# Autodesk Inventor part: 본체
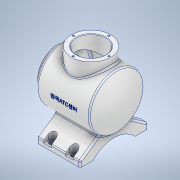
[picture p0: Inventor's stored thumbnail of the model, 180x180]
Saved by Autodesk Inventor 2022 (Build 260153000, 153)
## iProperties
Created: 2023-04
Part Number: 본체
Material: 알루미늄 6061
Document SubType Name: Modeling
Designer: Admin
Mass: 1296.7 g
Surface Area: 1060.45 cm^2
Volume: 480.258 cm^3
Density: 2.7 g/cm^3
Appearance: 알루미늄 - 평지
Author: Admin
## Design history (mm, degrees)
sketch "스케치1"
  geometry: L1 (-96.549, 0)-(166.291, 0) reference; L2 (0, -10.134)-(0, 60.805) reference; L3 (8.743, 0)-(128.743, 0); L4 (42.336, 50)-(-54, 50); L5 (-54, 50)-(-54, 43); L6 (-54, 0)-(54, 0); L7 (-54, 43)-(-54, 0); A1 r 113 centre (-59, 0) between (54, 0) and (42.336, 50); 3 further points
  constraints: 10 end point, 6 point on line, 2 perpendicular, 2 point on circle, 2 symmetric about line, 1 centre point, 1 collinear, 1 horizontal
  dimensions: "d2" = 113 radius of A1; "d4" = 108 distance from line of L6.end L5; "d75" = 100 diameter of L4 L1
revolve "회전1" sketch "스케치1" stored, may be unused: angle "d7" = 360 deg
sketch "스케치2"
  geometry: L1 (-77, -62)-(-77, 62); L2 (-134.515, 0)-(22.419, 0) reference; L3 (0, -110.456)-(0, 116.899) reference; L4 (-60, -77.977)-(-60, 84.42); L5 (-77, 62)-(-67, 62); L6 (-67, 62)-(-34.468, 15.54); L7 (-34.468, 15.54)-(-34.468, -15.54); L8 (-34.468, -15.54)-(-67, -62); L9 (-67, -62)-(-77, -62); A1 r 52.096 centre (-112.096, 0) between (-77, -38.5) and (-77, 38.5); 1 further point
  constraints: 14 end point, 4 symmetric about line, 2 point on circle, 2 point on line, 2 vertical, 1 centre point, 1 horizontal, 1 parallel, 1 perpendicular, 1 tangent
  dimensions: "d8" = 77 distance between parallel lines of L1 L3; "d9" = 124 distance of L1.start L1.end; "d11" = 77 distance of A1.end A1.start; "d12" = 17 distance between parallel lines of L1 L4; "d13" = 162.39677 distance of L4.start L4.end; "d14" = 55 deg angle of L6 L5; "d15" = 42.53177 distance between parallel lines of L1 L7; "d16" = 10 distance of L1.end L5.end
extrude "돌출1" join sketch "스케치2" distance "d17" = 38; taper "d18" = 0 deg; dims "d98" = 42, "d99" = 0
sketch "스케치12"
  geometry: L1 (38.5, -77)-(62, -77) reference; L2 (-86.8, 0)-(86.8, 0) reference; L3 (0, -102.4)-(0, 75.4) reference; C1 r 36 at (0, 0); 1 further point
  constraints: 1 centre point, 1 point on line
  dimensions: "d76" = 72 diameter of C1; "d77" = 77 distance from line of L1 C1.centre
extrude "돌출5" join sketch "스케치12" distance "d78" = 12; taper "d79" = 0 deg
node "작업 평면1"
sketch "스케치3"
  geometry: L1 (13, 23.5)-(13, 15.5); L2 (27, 23.5)-(27, 15.5); L3 (0, 23.5)-(80, 23.5) reference; L4 (0, 0)-(0, 23.5) reference; L5 (13, 23.5)-(27, 23.5); L6 (53, 23.5)-(53, 15.5); L7 (67, 23.5)-(67, 15.5); L8 (53, 23.5)-(67, 23.5); A1 r 7 centre (20, 15.5) between (13, 15.5) and (27, 15.5); A2 r 7 centre (60, 15.5) between (53, 15.5) and (67, 15.5); 1 further point
  constraints: 12 end point, 4 point on circle, 4 point on line, 4 tangent, 4 vertical, 2 centre point, 1 collinear, 1 perpendicular
  dimensions: "d20" = 14 distance between parallel lines of L2 L1; "d21" = 8 distance from line of L3 L1.end; "d22" = 20 distance from line of L4 A1.centre; "d23" = 14 distance between parallel lines of L7 L6; "d24" = 8 distance from line of L3 A2.centre; "d25" = 40 distance of A1.centre A2.centre
extrude "돌출2" cut sketch "스케치3" distance "d26" = 30; taper "d27" = 0 deg
node "작업 평면3"
sketch "스케치13"
  geometry: L1 (0, -102.4)-(0, 75.4) reference; L2 (-90, 0)-(78, 0) reference; L3 (-66, 36)-(-66, -36) reference; L4 (-66, 0)-(-47, 0); L5 (-47, 0)-(-47, 27); L6 (-47, 27)-(-66, 27); L7 (-66, 27)-(-66, 0); L8 (-47, 0)-(37.887, 0); L9 (37.887, 0)-(37.887, 43); L10 (37.887, 43)-(-47, 43); L11 (-47, 43)-(-47, 0); L12 (37.887, 0)-(47, 0); A1 r 113 centre (-59, 0) between (42.336, -50) and (42.336, 50) reference; A2 r 106 centre (-59, 0) between (47, 0) and (37.887, 43); 4 further points
  constraints: 18 end point, 4 parallel, 2 horizontal, 2 perpendicular, 2 point on circle, 1 centre point, 1 midpoint, 1 point on line
  dimensions: "d81" = 7 radial gap between concentric circles of A1 A2; "d82" = 54 diameter of L6 L2; "d83" = 86 diameter of L10 L2; "d84" = 19 distance of L5.end L6.end
revolve "회전3" sketch "스케치13" stored, may be unused: angle "d85" = 360 deg
sketch "스케치5"
  geometry: L1 (90, 0)-(-78, 0) reference; L2 (0, -86.8)-(0, 86.8) reference; L3 (66, -36)-(66, 36) reference; C1 r 36 at (4, 0); 1 further point
  constraints: 1 centre point, 1 point on line
  dimensions: "d35" = 72 diameter of C1; "d80" = 62 distance from line of L3 C1.centre
extrude "돌출3" join sketch "스케치5" stored distance "d37" = 30; taper "d38" = 0 deg
sketch "스케치6"
  geometry: C1 r 36 at (0, 0) reference; C2 r 27 at (0, 0); 1 further point
  constraints: 1 centre point, 1 coincident
  dimensions: "d39" = 54 diameter of C2
extrude "돌출4" cut sketch "스케치6" stored distance "d40" = 10; taper "d41" = 0 deg
sketch "스케치7"
  geometry: L1 (13, -23.5)-(13, -15.5) reference; L2 (27, -23.5)-(13, -23.5) reference; L3 (27, -15.5)-(27, -23.5) reference; L4 (53, -23.5)-(53, -15.5) reference; L5 (67, -23.5)-(53, -23.5) reference; L6 (67, -15.5)-(67, -23.5) reference; L7 (13, 100.5)-(13, 92.5) reference; L8 (27, 92.5)-(27, 100.5) reference; L9 (13, 100.5)-(27, 100.5) reference; L10 (53, 100.5)-(53, 92.5) reference; L11 (67, 92.5)-(67, 100.5) reference; L12 (53, 100.5)-(67, 100.5) reference; A1 r 7 centre (20, -15.5) between (27, -15.5) and (13, -15.5) reference; A2 r 7 centre (60, -15.5) between (67, -15.5) and (53, -15.5) reference; A3 r 7 centre (20, 92.5) between (13, 92.5) and (27, 92.5) reference; A4 r 7 centre (60, 92.5) between (53, 92.5) and (67, 92.5) reference; A5 r 7 centre (20, 92.5) between (13, 92.5) and (27, 92.5) reference; 5 further points
  constraints: 4 coincident
hole "구멍1" sketch "스케치7" at (20, 92.5), (60, 92.5), (20, -15.5), (60, -15.5) diameter "d42" = 9; stored, may be unused: countersink angle "d46" = 90 deg, drill point angle "d48" = 118 deg; dims "d43" = 6, "d44" = 4, "d45" = 2, "d47" = 8
sketch "스케치9" dims "d60" = 65
  geometry: L1 (0, 72.884)-(0, -78.398); C1 r 27 at (0, 0) reference; C2 r 36 at (0, 0) reference; 3 further points
  constraints: 2 end point, 2 point on line, 1 coincident, 1 vertical, 1 vertical alignment, 2 other
hole "구멍3" sketch "스케치9" at (0, 32.5) diameter "d61" = 3.242; stored, may be unused: countersink angle "d65" = 90 deg, drill point angle "d67" = 118 deg; dims "d62" = 8, "d63" = 4, "d64" = 2, "d66" = 10
node "작업 평면4"
sketch "스케치10"
  geometry: L1 (-90, 0)-(78, 0) reference; L2 (-66, 36)-(-66, -36) reference; 2 further points
  constraints: 1 point on line, 1 other
  dimensions: "d86" = 62 distance from line of L2 point (-4, 0)
feature "엠보싱1" sketch "스케치10" dims "d18" = 0, "d73" = 0.5, "d74" = 0
sketch "스케치14" dims "d87" = 65
  geometry: L1 (0, -102.4)-(0, 75.4) reference; C1 r 27 at (0, 0) reference; C2 r 36 at (0, 0) reference; 3 further points
  constraints: 1 coincident, 1 point on line, 1 vertical alignment, 2 other
hole "구멍4" sketch "스케치14" at (0, 32.5) diameter "d88" = 3.242; stored, may be unused: countersink angle "d92" = 90 deg, drill point angle "d94" = 118 deg; dims "d89" = 8, "d90" = 4, "d91" = 2, "d93" = 10
fillet "모깎기1" dims "d100" = 3
chamfer "모따기1" distance "d101" = 1; stored, may be unused: second distance "d102" = 2, angle "d103" = 45 deg
node "솔리드1"
mirror "미러1"
pattern_circular "원형 패턴2" dims angle "d69" = 360 deg
pattern_circular "원형 패턴3" dims angle "d96" = 360 deg
node "투영된 루프1"
node "투영된 루프2"
node "투영된 루프3"
node "투영된 루프4"
node "투영된 루프5"
node "투영된 루프7"
node "투영된 루프8"
feature "A9D066F2-1C7D-4E18-AEED-F7BC21143FA4" dims "d42" = 9, "d43" = 6, "d44" = 4, "d45" = 2, "d46" = 90 deg, "d47" = 8, "d48" = 118 deg
other parameters: "d19" = -6, "d34" = 65, "d71" = 153.75
